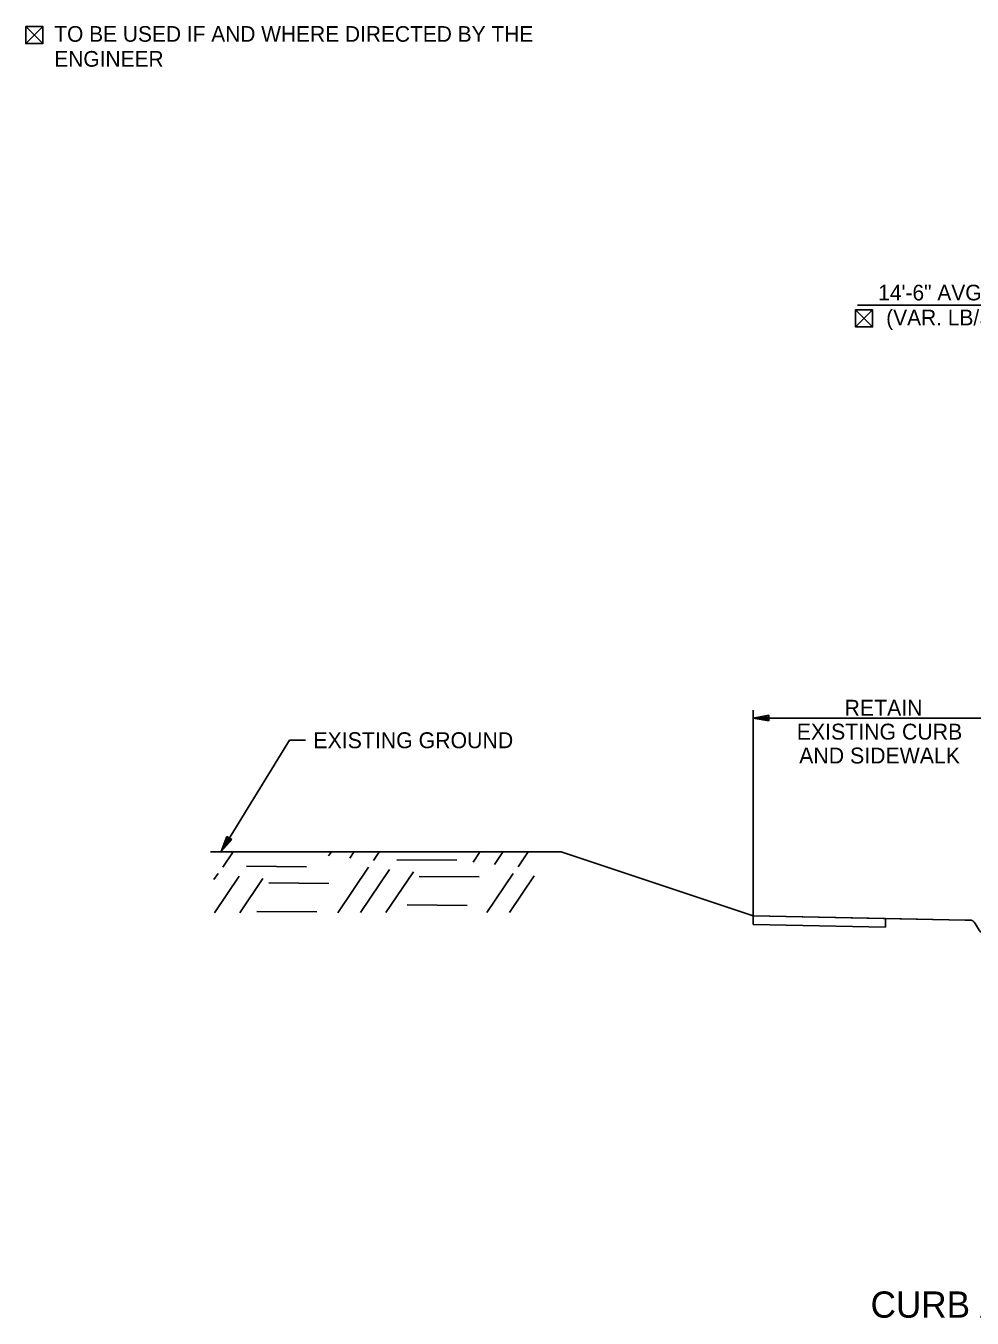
# Model space of a CAD drawing. Extents: x 1001270 to 1003428, y 1840152 to 1842912.
# Drawn here: x 1001815.28 to 1001850.96, y 1841965.71 to 1842014.41 of the extents above; entities that cross this region are included whole.
import ezdxf

# ---------------------------------------------------------------- set-up
doc = ezdxf.new("R2010")
doc.units = 0
for name, color, linetype in [('10', 7, 'Continuous'), ('19', 7, 'Continuous'), ('Default', 7, 'Continuous')]:
    doc.layers.add(name, color=color, linetype=linetype)

msp = doc.modelspace()

# ---------------------------------------------------------------- linework, layer by layer
at = {"layer": '10'}
for p, q in [((1001815.28, 1842014.384), (1001815.922, 1842013.743)), ((1001815.922, 1842014.384), (1001815.28, 1842013.743)), ((1001815.662, 1842013.743), (1001815.673, 1842013.743)), ((1001846.563, 1842003.707), (1001847.204, 1842003.065)), ((1001847.204, 1842003.706), (1001846.563, 1842003.065)), ((1001846.944, 1842003.065), (1001846.955, 1842003.065))]:
    msp.add_line(p, q, dxfattribs=at)
for points in [[(1001815.673, 1842013.743), (1001815.922, 1842013.743), (1001815.922, 1842014.384), (1001815.28, 1842014.384), (1001815.28, 1842013.743), (1001815.662, 1842013.743)], [(1001846.955, 1842003.065), (1001847.204, 1842003.065), (1001847.204, 1842003.706), (1001846.563, 1842003.707), (1001846.563, 1842003.065), (1001846.944, 1842003.065)]]:
    msp.add_lwpolyline(points, dxfattribs=at)
at = {"layer": '19'}
for p, q in [((1001891.194, 1842003.888), (1001846.632, 1842003.888)), ((1001842.7, 1841980.868), (1001842.7, 1841988.621)), ((1001843.3, 1841988.426), (1001842.7, 1841988.321)), ((1001842.7, 1841988.321), (1001843.3, 1841988.216)), ((1001853.879, 1841988.321), (1001842.7, 1841988.321)), ((1001843.3, 1841988.371), (1001842.86, 1841988.336)), ((1001842.86, 1841988.306), (1001843.3, 1841988.266)), ((1001843.3, 1841988.216), (1001843.3, 1841988.426)), ((1001822.64, 1841983.286), (1001822.864, 1841983.852)), ((1001823.042, 1841983.743), (1001822.64, 1841983.286)), ((1001822.714, 1841983.426), (1001822.907, 1841983.82)), ((1001823.001, 1841983.764), (1001822.737, 1841983.415)), ((1001822.864, 1841983.852), (1001823.042, 1841983.743)), ((1001822.712, 1841982.7), (1001823.104, 1841983.283)), ((1001826.697, 1841983.135), (1001826.803, 1841983.284)), ((1001827.492, 1841983.043), (1001827.658, 1841983.287)), ((1001828.387, 1841982.951), (1001828.613, 1841983.289)), ((1001832.152, 1841982.895), (1001832.413, 1841983.29)), ((1001832.946, 1841982.803), (1001833.278, 1841983.292)), ((1001833.842, 1841982.711), (1001834.222, 1841983.285)), ((1001823.601, 1841982.739), (1001825.86, 1841982.718)), ((1001827.049, 1841980.987), (1001828.202, 1841982.708)), ((1001829.275, 1841982.98), (1001831.536, 1841982.968)), ((1001822.372, 1841982.233), (1001822.526, 1841982.458)), ((1001822.395, 1841980.984), (1001823.321, 1841982.366)), ((1001823.35, 1841980.986), (1001824.216, 1841982.274)), ((1001827.904, 1841980.99), (1001828.996, 1841982.616)), ((1001828.859, 1841980.992), (1001829.892, 1841982.524)), ((1001830.105, 1841982.352), (1001832.376, 1841982.339)), ((1001832.66, 1841980.993), (1001833.656, 1841982.469)), ((1001833.514, 1841980.995), (1001834.451, 1841982.377)), ((1001824.441, 1841982.11), (1001826.7, 1841982.089)), ((1001829.663, 1841981.281), (1001831.923, 1841981.26)), ((1001823.988, 1841981.031), (1001826.258, 1841981.018)), ((1001847.699, 1841980.768), (1001842.7, 1841980.868)), ((1001842.7, 1841980.868), (1001842.7, 1841980.535)), ((1001847.699, 1841980.768), (1001850.697, 1841980.708)), ((1001847.699, 1841980.435), (1001847.699, 1841980.768)), ((1001847.699, 1841980.768), (1001847.699, 1841980.768)), ((1001842.7, 1841980.535), (1001847.699, 1841980.435))]:
    msp.add_line(p, q, dxfattribs=at)
for points in [[(1001825.823, 1841987.485), (1001825.223, 1841987.484), (1001822.64, 1841983.286)], [(1001822.244, 1841983.284), (1001835.469, 1841983.278)], [(1001835.469, 1841983.278), (1001842.7, 1841980.868), (1001850.697, 1841980.708), (1001850.864, 1841980.708), (1001850.928, 1841980.7), (1001850.989, 1841980.674), (1001851.04, 1841980.635), (1001851.08, 1841980.583), (1001851.226, 1841980.332), (1001851.266, 1841980.28), (1001851.32, 1841980.24), (1001851.383, 1841980.215), (1001851.447, 1841980.208), (1001851.913, 1841980.217), (1001852.197, 1841980.223), (1001855.158, 1841980.282), (1001866.695, 1841980.513)]]:
    msp.add_lwpolyline(points, dxfattribs=at)

# ---------------------------------------------------------------- texts
for s, height, p in [('14\'-6" AVG. ACHM SURFACE COURSE (1/2")', 0.59001, (1001847.42, 1842004.062)), ('(VAR. LB/SQ.YD LEVELING) & TACK COAT', 0.59001, (1001847.72, 1842003.122)), ('RETAIN', 0.6, (1001846.148, 1841988.409)), ('EXISTING CURB', 0.6, (1001844.348, 1841987.509)), ('EXISTING GROUND', 0.6, (1001826.123, 1841987.185)), ('AND SIDEWALK', 0.6, (1001844.44, 1841986.609))]:
    msp.add_text(s, height=height, dxfattribs=at).set_placement(p)
msp.add_text('CURB AND GUTTER SECTION W/ EXISTING MILL AND OVERLAY', height=0.98999, rotation=359.9954, dxfattribs=at).set_placement((1001847.131, 1841965.722))
at = {"layer": 'Default'}
for s, height, p in [('TO BE USED IF AND WHERE DIRECTED BY THE ', 0.59001, (1001816.353, 1842013.81)), ('ENGINEER', 0.59, (1001816.353, 1842012.87))]:
    msp.add_text(s, height=height, rotation=359.9954, dxfattribs=at).set_placement(p)

doc.saveas('drawing.dxf')
